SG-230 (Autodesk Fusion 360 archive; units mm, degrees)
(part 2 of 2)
sketch "Sketch1" plane through (0, 0, 14.7) normal (0, 0, 1) x axis (-1, 0, 0)
  curve K1 (-12.1252, 19.3156) -> (-13.686, 18.3553)
  curve K2 (-10.562, 18.3553) -> (-12.1252, 19.3156)
  curve K3 (-12.1228, 17.3974) -> (-10.562, 18.3553)
  curve K4 (-13.686, 18.3553) -> (-12.1228, 17.3974)
  line L1 (-7.2515, 12.8245) -> (-7.4921, 12.8245)
  line L2 (-6.2182, 10.6608) -> (-7.2515, 12.8245)
  line L3 (-6.5756, 10.6608) -> (-6.2182, 10.6608)
  line L4 (-7.3706, 12.3383) -> (-6.5756, 10.6608)
  line L5 (-8.168, 10.6608) -> (-7.3706, 12.3383)
  line L6 (-8.5254, 10.6608) -> (-8.168, 10.6608)
  line L7 (-7.4921, 12.8245) -> (-8.5254, 10.6608)
  curve K5 (-8.7466, 14.3196) -> (-8.4646, 13.6487)
  curve K6 (-8.4743, 14.9809) -> (-8.7466, 14.3196)
  curve K7 (-7.3657, 15.3115) -> (-8.4743, 14.9809)
  curve K8 (-6.1113, 14.9833) -> (-7.3657, 15.3115)
  curve K9 (-5.6275, 13.9671) -> (-6.1113, 14.9833)
  curve K10 (-5.6688, 13.6268) -> (-5.6275, 13.9671)
  line L8 (-6.0554, 13.6268) -> (-5.6688, 13.6268)
  line L9 (-6.0554, 13.6438) -> (-6.0554, 13.6268)
  curve K11 (-5.9751, 14.0206) -> (-6.0554, 13.6438)
  curve K12 (-6.9767, 14.8983) -> (-5.9751, 14.0206)
  curve K13 (-6.7677, 14.2735) -> (-6.9767, 14.8983)
  curve K14 (-6.9451, 13.6924) -> (-6.7677, 14.2735)
  curve K15 (-7.7109, 13.3666) -> (-6.9451, 13.6924)
  curve K16 (-8.4646, 13.6487) -> (-7.7109, 13.3666)
  line L10 (-5.6834, 16.4736) -> (-5.6834, 16.9647)
  line L11 (-8.6834, 15.4623) -> (-5.6834, 16.4736)
  line L12 (-8.6834, 15.8829) -> (-8.6834, 15.4623)
  line L13 (-7.8447, 16.1551) -> (-8.6834, 15.8829)
  line L14 (-7.8447, 17.3002) -> (-7.8447, 16.1551)
  line L15 (-8.6834, 17.5725) -> (-7.8447, 17.3002)
  line L16 (-8.6834, 17.976) -> (-8.6834, 17.5725)
  line L17 (-5.6834, 16.9647) -> (-8.6834, 17.976)
  curve K17 (-7.5651, 19.1916) -> (-7.2539, 18.2945)
  line L18 (-7.5651, 19.5295) -> (-7.5651, 19.1916)
  line L19 (-8.6834, 19.5295) -> (-7.5651, 19.5295)
  line L20 (-8.6834, 19.9282) -> (-8.6834, 19.5295)
  line L21 (-5.6834, 19.9282) -> (-8.6834, 19.9282)
  line L22 (-5.6834, 19.1746) -> (-5.6834, 19.9282)
  curve K18 (-5.8706, 18.3893) -> (-5.6834, 19.1746)
  curve K19 (-6.5878, 18.032) -> (-5.8706, 18.3893)
  curve K20 (-7.2539, 18.2945) -> (-6.5878, 18.032)
  line L23 (-8.168, 22.8018) -> (-8.5254, 22.8018)
  line L24 (-7.3706, 21.1243) -> (-8.168, 22.8018)
  line L25 (-6.5756, 22.8018) -> (-7.3706, 21.1243)
  line L26 (-6.2182, 22.8018) -> (-6.5756, 22.8018)
  line L27 (-7.2515, 20.6381) -> (-6.2182, 22.8018)
  line L28 (-7.4921, 20.6381) -> (-7.2515, 20.6381)
  line L29 (-8.5254, 22.8018) -> (-7.4921, 20.6381)
  line L30 (-13.6228, 20.9299) -> (-13.6228, 20.4996)
  line L31 (-10.6228, 21.9631) -> (-13.6228, 20.9299)
  line L32 (-10.6228, 21.5352) -> (-10.6228, 21.9631)
  line L33 (-13.1147, 20.7038) -> (-10.6228, 21.5352)
  line L34 (-10.6228, 19.8723) -> (-13.1147, 20.7038)
  line L35 (-10.6228, 19.4663) -> (-10.6228, 19.8723)
  line L36 (-13.6228, 20.4996) -> (-10.6228, 19.4663)
  line L37 (-16.51, 20.3315) -> (-21.346, 15.5186)
  line L38 (-14.0534, 17.8631) -> (-16.51, 20.3315)
  line L39 (-21.9512, 10.0031) -> (-14.0534, 17.8631)
  line L40 (-23.5909, 11.6506) -> (-21.9512, 10.0031)
  line L41 (-23.5909, -3.6077) -> (-23.5909, 11.6506)
  line L42 (-23.5909, -8.3081) -> (-23.5909, -5.0749)
  line L43 (-3.8417, -21.5057) -> (-11.3257, -21.5057)
  line L44 (11.3257, -21.5057) -> (3.2395, -21.5057)
  curve K21 (20.5745, -12.9406) -> (21.8648, -12.5773)
  line L45 (22.8191, -13.0505) -> (21.8648, -12.5773)
  line L46 (23.5909, 11.83) -> (23.5909, -11.83)
  line L47 (-11.83, 23.5909) -> (11.83, 23.5909)
  line L48 (4, -2.0193) -> (4, -7.2153)
  line L49 (-4, -7.2153) -> (-4, -2.0193)
  line L50 (-17.3882, -7.2153) -> (-4, -7.2153)
  line L51 (-18.3873, 6.2162) -> (-18.3873, -6.2162)
  line L52 (-4, 7.2153) -> (-17.3882, 7.2153)
  line L53 (-4, 2.0193) -> (-4, 7.2153)
  line L54 (4, 7.2153) -> (4, 2.0193)
  line L55 (17.3882, 7.2153) -> (4, 7.2153)
  line L56 (18.3873, -6.2162) -> (18.3873, 6.2162)
  line L57 (4, -7.2153) -> (17.3882, -7.2153)
  curve K22
  curve K23
  curve K24
  curve K25
  circle C1 centre (0, -10) radius 4.0436
  circle C2 centre (11.9447, -13.4008) radius 1.4913
  circle C3 centre (-12.4364, 13.9524) radius 1.4871
  arc A1 centre (-23.0261, -4.3413) radius 0.9258 clockwise from (-23.5909, -3.6077) to (-23.5909, -5.0749)
  arc A2 centre (-22.1874, -11.5002) radius 3.4871 clockwise from (-23.5909, -8.3081) to (-19.8236, -14.0639)
  closed curve K26 centre (-20.4303, -14.5053)
  arc A3 centre (0, 0) radius 24.3057 clockwise from (-11.3257, -21.5057) to (-19.8182, -14.0716)
  arc A4 centre (-3.842, -22.5079) radius 1.0022 clockwise from (-3.8417, -21.5057) to (-3.536, -21.5535)
  arc A5 centre (-0.3011, -23.0217) radius 3.5525 clockwise from (-3.536, -21.5535) to (2.9339, -21.5535)
  arc A6 centre (3.2398, -22.5079) radius 1.0022 clockwise from (2.9339, -21.5535) to (3.2395, -21.5057)
  arc A7 centre (0, 0) radius 24.3057 clockwise from (20.5745, -12.9406) to (11.3257, -21.5057)
  arc A8 centre (22.3745, -13.9469) radius 1.0006 clockwise from (22.8191, -13.0505) to (22.9093, -13.1012)
  arc A9 centre (0, 0) radius 26.3909 clockwise from (23.5909, -11.83) to (22.9093, -13.1012)
  arc A10 centre (0, 0) radius 26.3909 clockwise from (21.0119, 15.968) to (23.5909, 11.83)
  arc A11 centre (18.6806, 18.6957) radius 3.5882 clockwise from (21.0119, 15.968) to (15.9511, 21.0248)
  arc A12 centre (0, 0) radius 26.3909 clockwise from (11.83, 23.5909) to (15.9511, 21.0248)
  arc A13 centre (0, 0) radius 26.3909 clockwise from (-21.346, 15.5186) to (-11.83, 23.5909)
  arc A14 centre (0, 0) radius 4.4808 clockwise from (4, -2.0193) to (-4, -2.0193)
  closed curve K27 centre (-17.3863, -6.2143)
  closed curve K28 centre (-17.3863, 6.2143)
  arc A15 centre (0, 0) radius 4.4808 clockwise from (-4, 2.0193) to (4, 2.0193)
  closed curve K29 centre (17.3863, 6.2143)
  closed curve K30 centre (17.3863, -6.2143)
  point P111 (18.3873, 6.2162)
  point P113 (18.3873, -6.2162)
  coincident L46
  coincident P111
  coincident P113 K23
  dimension "d1" Text1-Height = 3
extrude "Extrude1" add sketch "Sketch1" along normal blind 0.1
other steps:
derived_base_feature "Derived Base Feature2"

design "OP-1042-D"
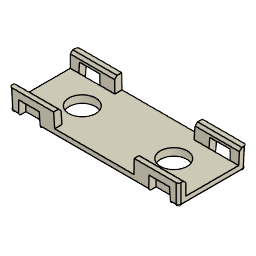
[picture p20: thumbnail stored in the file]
description: Part Number
part number: OP-1042-D
base_feature "Base Feature"
move_face "MoveFace1" TranslateX 0.85 TranslateY 0 TranslateZ 0
move_face "MoveFace2" TranslateX -0.4 TranslateY 0 TranslateZ 0
move_face "MoveFace3" TranslateX 0.4 TranslateY 0 TranslateZ 0
move_face "MoveFace4" TranslateX -0.85 TranslateY 0 TranslateZ 0

design "OP-1042-H"
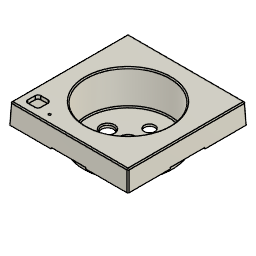
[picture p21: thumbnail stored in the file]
description: Part Number
part number: OP-1042-H
base_feature "Base Feature"
offset_faces "OffsetFaces1" distance -0.7
move_face "MoveFace1" TranslateX 0.793 TranslateY 0 TranslateZ 0
move_face "MoveFace2" TranslateX -0.793 TranslateY 0 TranslateZ 0
move_face "MoveFace3" TranslateX 1.701 TranslateY 0 TranslateZ 0
move_face "MoveFace4" TranslateX -1.701 TranslateY 0 TranslateZ 0

design "Spring Lock Washer DIN 127 - B 2 Steel 100 HV Plain"
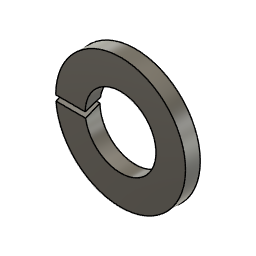
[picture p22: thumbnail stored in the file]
description: Part Number
part number: S_023.02.000.00031
parameter "adsk_woutdia" = 4.4
parameter "adsk_windia" = 2.4
parameter "adsk_wthick" = 0.5
sketch "Sketch1" plane through (0, 0, 0) normal (0, 0, 1) x axis (1, 0, 0)
  circle C1 centre (0, 0) radius 2.2
  circle C2 centre (0, 0) radius 1.2
  point P1 (0, 0)
  point P2 (0, 0)
  point P3 (0, 0)
  coincident P1 P2
  coincident P1 P3
  dimension "d4" diameter C1 = 4.4 (= "adsk_woutdia")
  dimension "d5" diameter C2 = 2.4 (= "adsk_windia")
extrude "Extrude1" new body sketch "Sketch1" along normal blind 0.5 (= "adsk_wthick")
work_plane "WorkPlane1" RotateAngle 20
work_plane "WorkPlane2" AlongDistance 0.25 (= "adsk_wthick / 2")
sketch "Sketch2" plane through (12.125, -0.0855, 0.2349) normal (0, -0.342, 0.9397) x axis (1, 0, 0)
  line L1 (-12.125, 0) -> (-12.125, 0.171)
  line L2 (-14.413, 0.171) -> (-12.125, 0.171)
  line L3 (-14.413, 0) -> (-12.125, 0)
  line L4 (-14.413, 0.171) -> (-14.413, 0)
  closed curve K1 centre (-12.125, 0.171)
  closed curve K2 centre (-12.125, 0)
  point P2 (-12.125, 0.171)
  point P4 (-12.125, 0.171)
  point P3 (-12.125, 0)
  point P5 (-12.125, 0)
  coincident P2 P4
  coincident P3 P5
  perpendicular L1 L2
  perpendicular L1 L3
  vertical L4
  dimension "d15" distance L1 L4 = 2.288 (= "adsk_woutdia * 0.52")
extrude "Extrude2" cut sketch "Sketch2" profile of K1 K2 L1 L2 L3 along a picked direction no distance stored
joint_origin "JointOrigin4" OffsetX 0 OffsetY 0 OffsetZ 0 AngleZ 0
joint_origin "JointOrigin6" OffsetX 0 OffsetY 0 OffsetZ 0.5 (= "adsk_wthick") AngleZ 0

design "bolec"
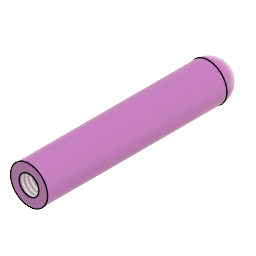
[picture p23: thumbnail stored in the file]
description: Part Number
part number: S_045.00.000.00102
